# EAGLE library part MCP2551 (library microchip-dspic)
High-Speed CAN Transceiver
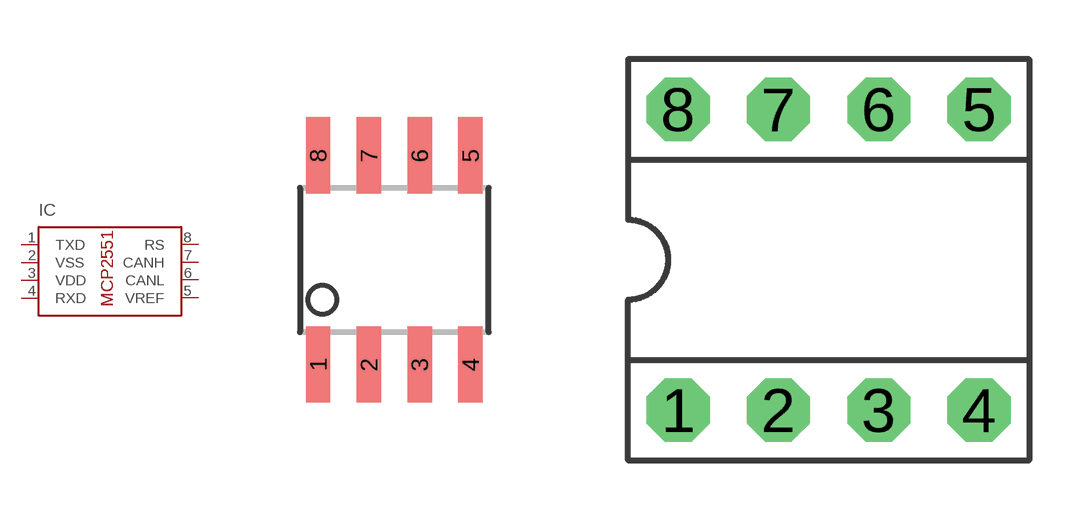
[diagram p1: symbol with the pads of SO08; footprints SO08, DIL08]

Designator prefix IC

## MCP2551/SN  [SO08]
1  TXD  in
2  VSS  pwr
3  VDD  pwr
4  RXD  out
5  VREF  out
6  CANL
7  CANH
8  RS  in

## MCP2551/P  [DIL08]
Pads as for SO08

## Footprint SO08 (pad centres in mm)
Small Outline Package
smd 0.61 x 1.905: 1 -1.905,-2.616; 2 -0.635,-2.616; 3 0.635,-2.616; 4 1.905,-2.616; 5 1.905,2.616; 6 0.635,2.616; 7 -0.635,2.616; 8 -1.905,2.616

## Footprint DIL08 (pad centres in mm)
Dual In Line
drill 0.813 pad 1.6 octagon: 1 -3.81,-3.81; 2 -1.27,-3.81; 3 1.27,-3.81; 4 3.81,-3.81; 5 3.81,3.81; 6 1.27,3.81; 7 -1.27,3.81; 8 -3.81,3.81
